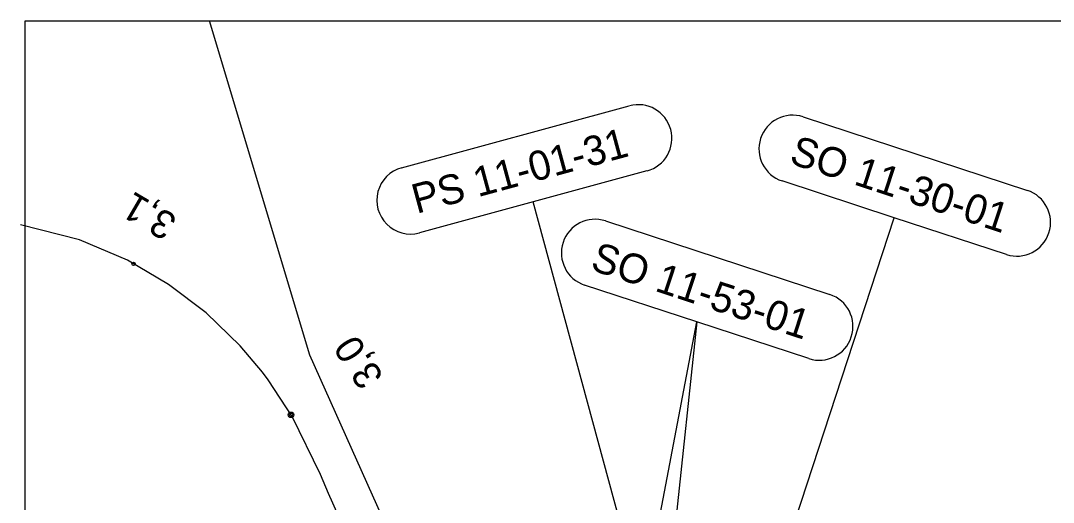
# Model space of a CAD drawing. Extents: x -728802 to -728097, y -1073200 to -1072700.
# Drawn here: x -728802.1 to -728342.4, y -1072914.2 to -1072700 of the extents above; entities that cross this region are included whole.
import ezdxf

# ---------------------------------------------------------------- set-up
doc = ezdxf.new("R2010")
doc.units = 0
for name, color, linetype in [('_popis', 7, 'Continuous'), ('JŽM', 7, 'Continuous'), ('K_31_listy_JŽM', 7, 'Continuous'), ('ZZZ_popisky', 7, 'Continuous')]:
    doc.layers.add(name, color=color, linetype=linetype)

msp = doc.modelspace()

# ---------------------------------------------------------------- linework, layer by layer
at = {"layer": '_popis'}
msp.add_lwpolyline([(-728800, -1073058.4), (-728506.43, -1073058.4), (-728512.81, -1073016.08), (-728565.8, -1073010.25), (-728631.48, -1072942.08), (-728673.37, -1072848.71), (-728717.99, -1072700)], dxfattribs=at)
at = {"layer": 'JŽM'}
msp.add_lwpolyline([(-728656.18, -1072930.07), (-728664.99, -1072910.23), (-728668.63, -1072901.81), (-728681.25, -1072876.02), (-728691.89, -1072859.66), (-728694.38, -1072856.37), (-728704.33, -1072844.56), (-728719.55, -1072829.89), (-728736.19, -1072817.3), (-728754.56, -1072806.55), (-728775.91, -1072797.5), (-728802.06, -1072790.86)], dxfattribs=at)
for centre, radius in [((-728751.8, -1072808.16), 0.75), ((-728681.73, -1072875.28), 1.25), ((-728681.73, -1072875.28), 0.752)]:
    msp.add_circle(centre, radius, dxfattribs=at)
at = {"layer": 'K_31_listy_JŽM'}
msp.add_lwpolyline([(-728800, -1073200), (-728800, -1072700), (-728100, -1072700), (-728100, -1073200), (-728800, -1073200)], dxfattribs=at)
at = {"layer": 'ZZZ_popisky'}
for p, q in [((-728541.71, -1072789.05), (-728441.93, -1072821.74)), ((-728501.16, -1072833.9), (-728527.4, -1073080.55)), ((-728451.27, -1072850.25), (-728501.16, -1072833.9))]:
    msp.add_line(p, q, dxfattribs=at)
for points in [[(-728632.48, -1072765.39), (-728531.15, -1072737.87)], [(-728453.77, -1072742.78), (-728353.99, -1072775.47)], [(-728523.28, -1072766.82), (-728573.95, -1072780.58)], [(-728496.07, -1073040.51), (-728413.22, -1072787.63), (-728463.11, -1072771.29)], [(-728504.21, -1073037.38), (-728573.95, -1072780.58), (-728624.61, -1072794.34)], [(-728363.33, -1072803.98), (-728413.22, -1072787.63)], [(-728537.32, -1073024.17), (-728501.16, -1072833.9), (-728551.05, -1072817.56)]]:
    msp.add_lwpolyline(points, dxfattribs=at)
for centre, start, end in [((-728527.21, -1072752.35), 285.1943, 105.1943), ((-728458.44, -1072757.03), 71.8591, 251.8591), ((-728628.54, -1072779.87), 105.1943, 285.1943), ((-728358.66, -1072789.73), 251.8591, 71.8591), ((-728546.38, -1072803.3), 71.8591, 251.8591), ((-728446.6, -1072836), 251.8591, 71.8591)]:
    msp.add_arc(centre, 15, start, end, dxfattribs=at)

# ---------------------------------------------------------------- texts
at = {"layer": 'JŽM'}
for s, rotation, p in [('3,1', 149.6763, (-728731.71, -1072787.46)), ('3,0', 123.0351, (-728640.18, -1072858.29))]:
    msp.add_text(s, height=12.5, rotation=rotation, dxfattribs=at).set_placement(p)
at = {"layer": 'ZZZ_popisky'}
for s, rotation, p in [('PS 11-01-31', 15.1943, (-728625.83, -1072785.93)), ('SO 11-30-01', 341.8591, (-728460.46, -1072763.28)), ('SO 11-53-01', 341.8591, (-728548.98, -1072810.63))]:
    msp.add_text(s, height=13.125, rotation=rotation, dxfattribs=at).set_placement(p)

doc.saveas('drawing.dxf')
